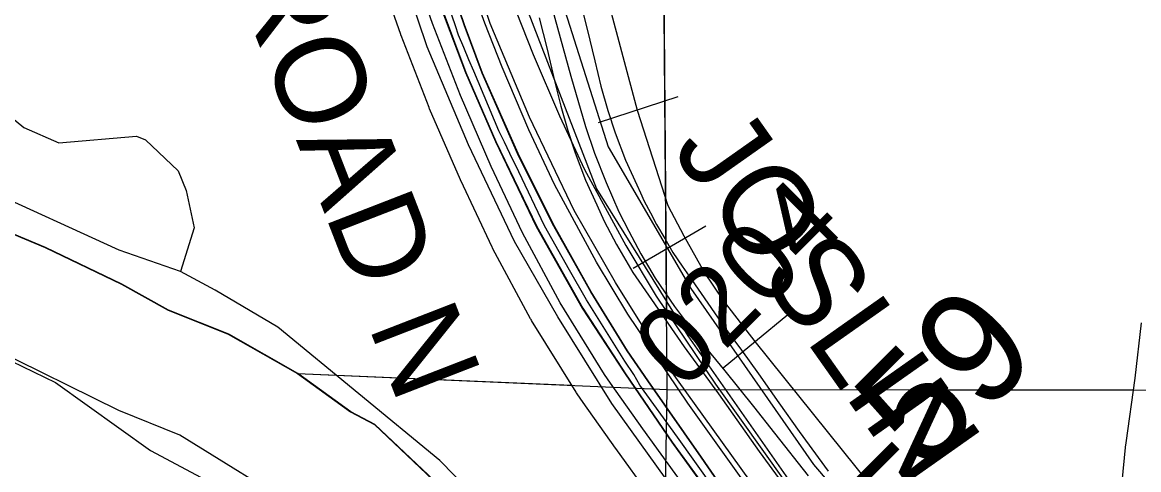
# Model space of a CAD drawing. Extents: x -132.8 to -73.3, y -60 to -26.
# Drawn here: x -124.268 to -123.269, y -45.375 to -44.975 of the extents above; entities that cross this region are included whole.
import ezdxf

# ---------------------------------------------------------------- set-up
doc = ezdxf.new("R2010")
doc.units = 0
for name, color, linetype in [('tdCoClipBndry', 7, 'Continuous'), ('tdCoCoBndry', 7, 'Continuous'), ('tdCoDivCarto', 7, 'Continuous'), ('tdCoHydroRiver', 7, 'Continuous'), ('tdCoInt', 7, 'Continuous'), ('tdCoIntCL', 7, 'Continuous'), ('tdCoIntRte', 7, 'Continuous'), ('tdCoPrimary', 7, 'Continuous'), ('tdCoRRCL', 7, 'Continuous'), ('tdCoSecRdNmbr', 7, 'Continuous'), ('tdCoSecRdTxt', 7, 'Continuous'), ('tdCoSecRteBand', 7, 'Continuous'), ('tdCoSecRteCL', 7, 'Continuous'), ('tdCoSectLine', 7, 'Continuous'), ('tdCoSectLinePart', 7, 'Continuous'), ('tdCoStBndry', 7, 'Continuous'), ('tdCoStBndryPart', 7, 'Continuous'), ('tdCoSurfGravel', 7, 'Continuous'), ('tdCoTwpBndryShd', 7, 'Continuous'), ('tdStHwyIntRefPost1', 7, 'Continuous')]:
    doc.layers.add(name, color=color, linetype=linetype)

msp = doc.modelspace()

# ---------------------------------------------------------------- linework, layer by layer
at = {"layer": 'tdCoClipBndry'}
msp.add_lwpolyline([(-124.01511, -45.41316), (-124.12675, -45.34419), (-124.18134, -45.32205), (-124.40871, -45.21001), (-124.50766, -45.1763), (-124.57794, -45.15917), (-124.65494, -45.14965), (-124.79577, -45.14308), (-124.898, -45.14486), (-125.21642, -45.18326), (-125.4103, -45.23569), (-125.73672, -45.23796), (-125.88496, -45.21905), (-126.11434, -45.13247), (-126.53414, -44.87623), (-126.77109, -44.70765), (-127.14208, -44.40767)], dxfattribs=at)
at = {"layer": 'tdCoCoBndry'}
for p, q in [((-124.24673, -45.17619), (-124.30613, -45.15157)), ((-124.17849, -45.20902), (-124.24673, -45.17619)), ((-124.13678, -45.23238), (-124.17849, -45.20902)), ((-124.08307, -45.25384), (-124.13678, -45.23238)), ((-124.02117, -45.28877), (-124.08307, -45.25384)), ((-123.97374, -45.3233), (-124.02117, -45.28877)), ((-123.95225, -45.33467), (-123.97374, -45.3233)), ((-123.8941, -45.38961), (-123.95225, -45.33467))]:
    msp.add_line(p, q, dxfattribs=at)
for points in [[(-125.23594, -45.08493), (-125.14117, -45.07226), (-125.04956, -45.06338), (-124.95858, -45.05197), (-124.90488, -45.045), (-124.79431, -45.04307), (-124.71752, -45.04881), (-124.64647, -45.04997), (-124.5599, -45.06068), (-124.47965, -45.08023), (-124.41204, -45.10169), (-124.37034, -45.11747), (-124.30651, -45.15157), (-124.24711, -45.17619), (-124.17886, -45.20902), (-124.13716, -45.23238), (-124.08344, -45.25384), (-124.02155, -45.28877), (-123.97412, -45.3233), (-123.95263, -45.33467), (-123.89448, -45.38961)], [(-123.8941, -45.38961), (-123.95225, -45.33467), (-123.97374, -45.3233), (-124.02117, -45.28877), (-124.08307, -45.25384), (-124.13678, -45.23238), (-124.17849, -45.20902), (-124.24673, -45.17619), (-124.30613, -45.15157), (-124.36996, -45.11747), (-124.41166, -45.10169), (-124.47928, -45.08023), (-124.55952, -45.06068), (-124.64609, -45.04997), (-124.71714, -45.04881), (-124.79393, -45.04307), (-124.9045, -45.045), (-124.9582, -45.05197), (-125.04918, -45.06338), (-125.14079, -45.07226), (-125.23556, -45.08493)]]:
    msp.add_lwpolyline(points, dxfattribs=at)
at = {"layer": 'tdCoDivCarto'}
for p, q in [((-123.87221, -44.97694), (-123.88947, -44.92614)), ((-123.89226, -44.96304), (-123.87106, -45.01952)), ((-123.85618, -45.02034), (-123.87221, -44.97694)), ((-123.87106, -45.01952), (-123.84417, -45.08142)), ((-123.82436, -45.0921), (-123.85618, -45.02034)), ((-123.84417, -45.08142), (-123.80768, -45.15737)), ((-123.79305, -45.15499), (-123.82436, -45.0921)), ((-123.75901, -45.2159), (-123.79305, -45.15499)), ((-123.80768, -45.15737), (-123.76649, -45.23037)), ((-123.72646, -45.26867), (-123.75901, -45.2159)), ((-123.76649, -45.23037), (-123.72827, -45.28931)), ((-123.70797, -45.29555), (-123.72646, -45.26867)), ((-123.72827, -45.28931), (-123.68659, -45.35046)), ((-123.66037, -45.36362), (-123.70797, -45.29555)), ((-123.68659, -45.35046), (-123.65626, -45.39214)), ((-123.61855, -45.42416), (-123.66037, -45.36362))]:
    msp.add_line(p, q, dxfattribs=at)
for points in [[(-123.61855, -45.42416), (-123.66037, -45.36362), (-123.70797, -45.29555), (-123.72646, -45.26867), (-123.75901, -45.2159), (-123.79305, -45.15499), (-123.82436, -45.0921), (-123.85618, -45.02034), (-123.87221, -44.97694), (-123.88947, -44.92614), (-123.90722, -44.86843), (-123.93805, -44.76264), (-123.97381, -44.63785), (-124.00266, -44.53674), (-124.03201, -44.43563), (-124.06924, -44.30666), (-124.09982, -44.22059), (-124.14862, -44.09419)], [(-123.61855, -45.42416), (-123.66037, -45.36362), (-123.70797, -45.29555), (-123.72646, -45.26867), (-123.75901, -45.2159), (-123.79305, -45.15499), (-123.82436, -45.0921), (-123.85618, -45.02034), (-123.87221, -44.97694), (-123.88947, -44.92614), (-123.90722, -44.86843), (-123.93805, -44.76264), (-123.97381, -44.63785), (-124.00266, -44.53674), (-124.03201, -44.43563), (-124.06924, -44.30666), (-124.09982, -44.22059), (-124.14862, -44.09419)], [(-123.61855, -45.42416), (-123.66037, -45.36362), (-123.70797, -45.29555), (-123.72646, -45.26867), (-123.75901, -45.2159), (-123.79305, -45.15499), (-123.82436, -45.0921), (-123.85618, -45.02034), (-123.87221, -44.97694), (-123.88947, -44.92614), (-123.90722, -44.86843), (-123.93805, -44.76264), (-123.97381, -44.63785), (-124.00266, -44.53674), (-124.03201, -44.43563), (-124.06924, -44.30666), (-124.09982, -44.22059), (-124.14862, -44.09419)], [(-124.15734, -44.11037), (-124.1443, -44.14431), (-124.10508, -44.24493), (-124.07599, -44.32976), (-124.06834, -44.35836), (-124.0316, -44.48364), (-123.99707, -44.60472), (-123.96255, -44.72507), (-123.93172, -44.83382), (-123.91125, -44.9078), (-123.89226, -44.96304), (-123.87106, -45.01952), (-123.84417, -45.08142), (-123.80768, -45.15737), (-123.76649, -45.23037), (-123.72827, -45.28931), (-123.68659, -45.35046), (-123.65626, -45.39214)], [(-124.15734, -44.11037), (-124.1443, -44.14431), (-124.10508, -44.24493), (-124.07599, -44.32976), (-124.06834, -44.35836), (-124.0316, -44.48364), (-123.99707, -44.60472), (-123.96255, -44.72507), (-123.93172, -44.83382), (-123.91125, -44.9078), (-123.89226, -44.96304), (-123.87106, -45.01952), (-123.84417, -45.08142), (-123.80768, -45.15737), (-123.76649, -45.23037), (-123.72827, -45.28931), (-123.68659, -45.35046), (-123.65626, -45.39214)], [(-124.15734, -44.11037), (-124.1443, -44.14431), (-124.10508, -44.24493), (-124.07599, -44.32976), (-124.06834, -44.35836), (-124.0316, -44.48364), (-123.99707, -44.60472), (-123.96255, -44.72507), (-123.93172, -44.83382), (-123.91125, -44.9078), (-123.89226, -44.96304), (-123.87106, -45.01952), (-123.84417, -45.08142), (-123.80768, -45.15737), (-123.76649, -45.23037), (-123.72827, -45.28931), (-123.68659, -45.35046), (-123.65626, -45.39214)]]:
    msp.add_lwpolyline(points, dxfattribs=at)
at = {"layer": 'tdCoHydroRiver'}
for points in [[(-124.12618, -45.19755), (-124.18089, -45.17863), (-124.30243, -45.1231), (-124.39926, -45.0872), (-124.53842, -45.04063), (-124.66387, -45.01181), (-124.74609, -45.01735), (-124.75858, -45.01226), (-124.77692, -44.99122), (-124.81648, -44.99483), (-124.82945, -45.00708), (-124.84987, -45.00334), (-124.87799, -44.99307), (-124.91759, -44.99825), (-124.94485, -45.01325), (-125.09373, -45.03109), (-125.25981, -45.0437)], [(-124.28004, -45.05747), (-124.26616, -45.06891), (-124.23498, -45.08242), (-124.16536, -45.07652), (-124.15756, -45.0799), (-124.12836, -45.10755), (-124.12097, -45.12512), (-124.11402, -45.15845), (-124.12618, -45.19755)], [(-125.28124, -45.18666), (-125.02725, -45.13553), (-124.95146, -45.13454), (-124.57854, -45.17517), (-124.54411, -45.18562), (-124.4927, -45.20917), (-124.43628, -45.2234), (-124.40627, -45.22269), (-124.38621, -45.23903), (-124.35823, -45.25403), (-124.29709, -45.2684), (-124.23791, -45.29691), (-124.15283, -45.35771), (-124.07199, -45.40104)], [(-123.79148, -45.47215), (-123.89423, -45.36667), (-124.03921, -45.24736), (-124.09509, -45.21421), (-124.12618, -45.19755)]]:
    msp.add_lwpolyline(points, dxfattribs=at)
at = {"layer": 'tdCoInt'}
for points in [[(-123.55308, -45.57692), (-123.74046, -45.31564), (-123.78872, -45.23836), (-123.82739, -45.17068), (-123.86875, -45.08428), (-123.90571, -44.99656), (-123.93096, -44.92117), (-124.01462, -44.62805), (-124.03288, -44.56973), (-124.08447, -44.38971), (-124.10278, -44.32357), (-124.14273, -44.21452), (-124.20021, -44.06525), (-124.29087, -43.83017), (-124.324, -43.74537), (-124.43508, -43.45911), (-124.47376, -43.36588), (-124.49814, -43.31328), (-124.54093, -43.2359), (-124.61351, -43.13317), (-124.65737, -43.06122), (-124.71285, -42.96855), (-124.75858, -42.87103), (-124.76764, -42.84773)], [(-123.50419, -45.54213), (-123.69017, -45.28281), (-123.7373, -45.20743), (-123.77409, -45.14305), (-123.81407, -45.05953), (-123.84932, -44.97587), (-123.87364, -44.90342), (-123.95712, -44.61088), (-123.97527, -44.55295), (-124.02677, -44.37325), (-124.04575, -44.3047), (-124.08652, -44.19353), (-124.14442, -44.04318), (-124.1625, -43.99862), (-124.16218, -43.99944), (-124.23494, -43.80842), (-124.26849, -43.72257), (-124.37939, -43.43676), (-124.41879, -43.3418), (-124.44443, -43.28648)]]:
    msp.add_lwpolyline(points, dxfattribs=at)
at = {"layer": 'tdCoIntCL'}
msp.add_lwpolyline([(-123.64916, -45.39147), (-123.68187, -45.34586), (-123.71532, -45.29922), (-123.71811, -45.29451), (-123.7209, -45.28979), (-123.72901, -45.27773), (-123.76301, -45.22289), (-123.77837, -45.19657), (-123.80074, -45.15687), (-123.82376, -45.10836), (-123.83159, -45.09219), (-123.8365, -45.08205), (-123.84141, -45.0719), (-123.86395, -45.01846), (-123.8683, -45.00815), (-123.87291, -44.99718), (-123.87751, -44.98622), (-123.88014, -44.97788), (-123.89243, -44.94213)], dxfattribs=at)
at = {"layer": 'tdCoIntRte'}
for points in [[(-123.61893, -45.42416), (-123.66075, -45.36362), (-123.70834, -45.29555), (-123.72684, -45.26867), (-123.75939, -45.2159), (-123.79342, -45.15499), (-123.82474, -45.0921), (-123.85656, -45.02034), (-123.87258, -44.97694), (-123.88985, -44.92614), (-123.9076, -44.86843), (-123.93843, -44.76264), (-123.97419, -44.63785), (-124.00304, -44.53674), (-124.03239, -44.43563), (-124.06962, -44.30666), (-124.1002, -44.22059), (-124.149, -44.09419)], [(-123.61893, -45.42416), (-123.66075, -45.36362), (-123.70834, -45.29555), (-123.72684, -45.26867), (-123.75939, -45.2159), (-123.79342, -45.15499), (-123.82474, -45.0921), (-123.85656, -45.02034), (-123.87258, -44.97694), (-123.88985, -44.92614), (-123.9076, -44.86843), (-123.93843, -44.76264), (-123.97419, -44.63785), (-124.00304, -44.53674), (-124.03239, -44.43563), (-124.06962, -44.30666), (-124.1002, -44.22059), (-124.149, -44.09419)], [(-124.14467, -44.14431), (-124.10546, -44.24493), (-124.07636, -44.32976), (-124.06872, -44.35836), (-124.03197, -44.48364), (-123.99745, -44.60472), (-123.96292, -44.72507), (-123.9321, -44.83382), (-123.91163, -44.9078), (-123.89264, -44.96304), (-123.87143, -45.01952), (-123.84455, -45.08142), (-123.80806, -45.15737), (-123.76687, -45.23037), (-123.72865, -45.28931), (-123.68697, -45.35046), (-123.65664, -45.39214)], [(-124.14467, -44.14431), (-124.10546, -44.24493), (-124.07636, -44.32976), (-124.06872, -44.35836), (-124.03197, -44.48364), (-123.99745, -44.60472), (-123.96292, -44.72507), (-123.9321, -44.83382), (-123.91163, -44.9078), (-123.89264, -44.96304), (-123.87143, -45.01952), (-123.84455, -45.08142), (-123.80806, -45.15737), (-123.76687, -45.23037), (-123.72865, -45.28931), (-123.68697, -45.35046), (-123.65664, -45.39214)]]:
    msp.add_lwpolyline(points, dxfattribs=at)
at = {"layer": 'tdCoPrimary'}
for points in [[(-123.61855, -45.42416), (-123.66037, -45.36362), (-123.70797, -45.29555), (-123.72646, -45.26867), (-123.75901, -45.2159), (-123.79305, -45.15499), (-123.82436, -45.0921), (-123.85618, -45.02034), (-123.87221, -44.97694), (-123.88947, -44.92614), (-123.90722, -44.86843), (-123.93805, -44.76264), (-123.97381, -44.63785), (-124.00266, -44.53674), (-124.03201, -44.43563), (-124.06924, -44.30666), (-124.09982, -44.22059), (-124.14862, -44.09419)], [(-123.61855, -45.42416), (-123.66037, -45.36362), (-123.70797, -45.29555), (-123.72646, -45.26867), (-123.75901, -45.2159), (-123.79305, -45.15499), (-123.82436, -45.0921), (-123.85618, -45.02034), (-123.87221, -44.97694), (-123.88947, -44.92614), (-123.90722, -44.86843), (-123.93805, -44.76264), (-123.97381, -44.63785), (-124.00266, -44.53674), (-124.03201, -44.43563), (-124.06924, -44.30666), (-124.09982, -44.22059), (-124.14862, -44.09419)], [(-123.61855, -45.42416), (-123.66037, -45.36362), (-123.70797, -45.29555), (-123.72646, -45.26867), (-123.75901, -45.2159), (-123.79305, -45.15499), (-123.82436, -45.0921), (-123.85618, -45.02034), (-123.87221, -44.97694), (-123.88947, -44.92614), (-123.90722, -44.86843), (-123.93805, -44.76264), (-123.97381, -44.63785), (-124.00266, -44.53674), (-124.03201, -44.43563), (-124.06924, -44.30666), (-124.09982, -44.22059), (-124.14862, -44.09419)], [(-124.15734, -44.11037), (-124.1443, -44.14431), (-124.10508, -44.24493), (-124.07599, -44.32976), (-124.06834, -44.35836), (-124.0316, -44.48364), (-123.99707, -44.60472), (-123.96255, -44.72507), (-123.93172, -44.83382), (-123.91125, -44.9078), (-123.89226, -44.96304), (-123.87106, -45.01952), (-123.84417, -45.08142), (-123.80768, -45.15737), (-123.76649, -45.23037), (-123.72827, -45.28931), (-123.68659, -45.35046), (-123.65626, -45.39214)], [(-124.15734, -44.11037), (-124.1443, -44.14431), (-124.10508, -44.24493), (-124.07599, -44.32976), (-124.06834, -44.35836), (-124.0316, -44.48364), (-123.99707, -44.60472), (-123.96255, -44.72507), (-123.93172, -44.83382), (-123.91125, -44.9078), (-123.89226, -44.96304), (-123.87106, -45.01952), (-123.84417, -45.08142), (-123.80768, -45.15737), (-123.76649, -45.23037), (-123.72827, -45.28931), (-123.68659, -45.35046), (-123.65626, -45.39214)], [(-124.1443, -44.14431), (-124.10508, -44.24493), (-124.07599, -44.32976), (-124.06834, -44.35836), (-124.0316, -44.48364), (-123.99707, -44.60472), (-123.96255, -44.72507), (-123.93172, -44.83382), (-123.91125, -44.9078), (-123.89226, -44.96304), (-123.87106, -45.01952), (-123.84417, -45.08142), (-123.80768, -45.15737), (-123.76649, -45.23037), (-123.72827, -45.28931), (-123.68659, -45.35046), (-123.65626, -45.39214)]]:
    msp.add_lwpolyline(points, dxfattribs=at)
at = {"layer": 'tdCoRRCL'}
for p, q in [((-123.68134, -45.04128), (-123.75257, -45.06476)), ((-123.72135, -45.19464), (-123.65657, -45.15685)), ((-123.58323, -45.2363), (-123.64109, -45.28402))]:
    msp.add_line(p, q, dxfattribs=at)
for points in [[(-124.56441, -39.58277), (-124.59502, -40.99697), (-124.62126, -41.69986), (-124.64443, -42.5874), (-124.61743, -42.70169), (-124.59894, -42.77948), (-124.57448, -42.87004), (-124.36447, -43.41034), (-124.28789, -43.62059), (-124.20724, -43.85618), (-124.00071, -44.40901), (-123.83109, -44.9246), (-123.75422, -45.12382), (-123.67243, -45.25532), (-123.34073, -45.72941), (-123.31155, -45.76015), (-123.21558, -45.95355), (-123.18597, -46.02848), (-123.11918, -46.43252), (-123.02482, -47.17174), (-122.96612, -47.70495)], [(-123.58232, -40.4714), (-123.59666, -41.26294), (-123.63242, -42.39151), (-123.63672, -42.43557), (-123.64126, -42.54903), (-123.65963, -42.64794), (-123.68385, -42.72933), (-123.79029, -42.93793), (-123.83057, -43.02995), (-123.8684, -43.14885), (-123.90323, -43.27414), (-123.92804, -43.49908), (-123.92555, -43.88723), (-123.90748, -43.92083), (-123.9211, -44.44265), (-123.92029, -44.53259), (-123.90156, -44.60092), (-123.84732, -44.7601), (-123.74377, -45.08623), (-123.66974, -45.2128), (-123.56021, -45.37027), (-123.43616, -45.51551)], [(-123.45627, -45.45467), (-123.61223, -45.2604), (-123.6285, -45.23945), (-123.64056, -45.22346), (-123.65786, -45.19803), (-123.67594, -45.16618), (-123.6901, -45.13879), (-123.71762, -45.05358), (-123.78172, -44.81317), (-123.85988, -44.57574), (-123.87319, -44.53731), (-123.88574, -44.49111), (-123.89252, -44.46047), (-123.89503, -44.44007), (-123.89608, -44.3976), (-123.89594, -44.34225), (-123.89553, -44.09233)], [(-123.79622, -44.95329), (-123.77708, -45.02276), (-123.76398, -45.06785), (-123.75611, -45.0917), (-123.74563, -45.11818), (-123.73409, -45.1444), (-123.72518, -45.1617), (-123.71469, -45.18188), (-123.70185, -45.20364), (-123.68455, -45.22907), (-123.66043, -45.26105), (-123.63946, -45.28648), (-123.61377, -45.31846), (-123.59516, -45.34231), (-123.56501, -45.38032)], [(-123.8055, -44.97058), (-123.79842, -44.99863), (-123.7916, -45.02694), (-123.7861, -45.04975), (-123.77981, -45.07151), (-123.77325, -45.09143), (-123.76408, -45.11581), (-123.75386, -45.13809), (-123.7473, -45.15251), (-123.73635, -45.17336), (-123.73629, -45.17348), (-123.72161, -45.19864), (-123.7051, -45.22276), (-123.67574, -45.26497), (-123.64507, -45.30717), (-123.60889, -45.35881), (-123.58294, -45.3942)], [(-123.76616, -44.96672), (-123.76262, -44.98075), (-123.7558, -45.00906), (-123.7503, -45.03186), (-123.744, -45.05362), (-123.73745, -45.07354), (-123.72828, -45.09792), (-123.72316, -45.10906), (-123.71805, -45.12021), (-123.71478, -45.12741), (-123.7115, -45.13462), (-123.70602, -45.14505), (-123.70055, -45.15548), (-123.69315, -45.16818), (-123.68581, -45.18076), (-123.67755, -45.19282), (-123.66929, -45.20488), (-123.65461, -45.22598), (-123.63993, -45.24708), (-123.6246, -45.26818), (-123.60926, -45.28929), (-123.59118, -45.31511), (-123.57309, -45.34093), (-123.54714, -45.37632)]]:
    msp.add_lwpolyline(points, dxfattribs=at)
at = {"layer": 'tdCoSecRteBand'}
for points in [[(-123.64653, -45.48115), (-123.73701, -45.35592), (-123.7371, -45.35578), (-123.7372, -45.35565), (-123.76608, -45.31471), (-123.77148, -45.30707), (-123.772, -45.30633), (-123.77247, -45.30556), (-123.81218, -45.24145), (-123.81265, -45.24068), (-123.81307, -45.23989), (-123.84686, -45.17726), (-123.84726, -45.17651), (-123.84762, -45.17575), (-123.87548, -45.11632), (-123.87566, -45.11595), (-123.87582, -45.11557), (-123.90344, -45.05219), (-123.90369, -45.05162), (-123.90392, -45.05103), (-123.92883, -44.98667), (-123.92902, -44.98618), (-123.92919, -44.98568), (-123.94546, -44.93883)], [(-123.82598, -44.96504), (-123.81078, -45.00339), (-123.78722, -45.05854), (-123.76487, -45.10636), (-123.72811, -45.17432), (-123.70099, -45.21967), (-123.64791, -45.29831), (-123.56331, -45.41686)], [(-123.28894, -45.43472), (-123.2808, -45.3521), (-123.28074, -45.3515), (-123.28065, -45.35089), (-123.27257, -45.29309), (-123.267, -45.24368)]]:
    msp.add_lwpolyline(points, dxfattribs=at)
at = {"layer": 'tdCoSecRteCL'}
for points in [[(-123.58773, -45.43429), (-123.67256, -45.31542), (-123.72632, -45.23577), (-123.75419, -45.18916), (-123.79167, -45.11986), (-123.81461, -45.07079), (-123.83853, -45.01481), (-123.85406, -44.9756), (-123.86319, -44.94995), (-123.88588, -44.88189), (-123.90067, -44.82837), (-123.93618, -44.70581), (-123.9421, -44.68485), (-123.94531, -44.66808), (-123.94679, -44.65008), (-123.94703, -44.61728), (-123.94605, -44.58103), (-123.94358, -44.51494), (-123.94334, -44.45772), (-123.94728, -44.33763), (-123.95006, -44.29303), (-123.95098, -44.27819), (-123.95147, -44.22616), (-123.94876, -44.14601)], [(-123.62218, -45.46363), (-123.71269, -45.33835), (-123.74157, -45.29741), (-123.74697, -45.28977), (-123.78667, -45.22565), (-123.82045, -45.16301), (-123.84832, -45.10358), (-123.87594, -45.0402), (-123.90085, -44.97584), (-123.91712, -44.92899), (-123.94277, -44.84095), (-123.97878, -44.71468), (-124.01478, -44.58916), (-124.02711, -44.54847), (-124.03278, -44.53762), (-124.04166, -44.52726), (-124.05128, -44.51962), (-124.06238, -44.51395), (-124.07224, -44.51049), (-124.08358, -44.50877), (-124.24769, -44.50526)]]:
    msp.add_lwpolyline(points, dxfattribs=at)
at = {"layer": 'tdCoSectLine'}
for points in [[(-123.69087, -45.30309), (-123.69916, -44.29255)], [(-124.71752, -45.04881), (-124.64647, -45.04997), (-124.5599, -45.06068), (-124.47965, -45.08023), (-124.41204, -45.10169), (-124.37034, -45.11747), (-124.30651, -45.15157), (-124.24711, -45.17619), (-124.17886, -45.20902), (-124.13716, -45.23238), (-124.08344, -45.25384), (-124.02155, -45.28877)], [(-124.02155, -45.28877), (-123.69087, -45.30309)], [(-124.02155, -45.28877), (-123.97412, -45.3233), (-123.95263, -45.33467), (-123.89448, -45.38961), (-123.85657, -45.43137), (-123.79202, -45.50244), (-123.77088, -45.52572), (-123.72719, -45.57383), (-123.69602, -45.60815)], [(-123.69602, -45.60815), (-123.69087, -45.30309)], [(-123.69087, -45.30309), (-122.72574, -45.3043)]]:
    msp.add_lwpolyline(points, dxfattribs=at)
at = {"layer": 'tdCoSectLinePart'}
for points in [[(-123.69144, -45.23441), (-123.69916, -44.29255)], [(-124.71752, -45.04881), (-124.64647, -45.04997), (-124.5599, -45.06068), (-124.47965, -45.08023), (-124.41204, -45.10169), (-124.37034, -45.11747), (-124.30651, -45.15157), (-124.24711, -45.17619), (-124.17886, -45.20902), (-124.13716, -45.23238), (-124.08344, -45.25384), (-124.02155, -45.28877)], [(-124.02155, -45.28877), (-123.77662, -45.29937)], [(-124.02155, -45.28877), (-123.97412, -45.3233), (-123.95263, -45.33467), (-123.89448, -45.38961), (-123.85657, -45.43137), (-123.79202, -45.50244), (-123.77088, -45.52572), (-123.72719, -45.57383), (-123.69602, -45.60815)], [(-123.64488, -45.30315), (-123.27499, -45.30361)]]:
    msp.add_lwpolyline(points, dxfattribs=at)
at = {"layer": 'tdCoStBndry'}
msp.add_lwpolyline([(-125.23594, -45.08493), (-125.14117, -45.07226), (-125.04956, -45.06338), (-124.95858, -45.05197), (-124.90488, -45.045), (-124.79431, -45.04307), (-124.71752, -45.04881), (-124.64647, -45.04997), (-124.5599, -45.06068), (-124.47965, -45.08023), (-124.41204, -45.10169), (-124.37034, -45.11747), (-124.30651, -45.15157), (-124.24711, -45.17619), (-124.17886, -45.20902), (-124.13716, -45.23238), (-124.08344, -45.25384), (-124.02155, -45.28877), (-123.97412, -45.3233), (-123.95263, -45.33467), (-123.89448, -45.38961)], dxfattribs=at)
at = {"layer": 'tdCoStBndryPart'}
msp.add_lwpolyline([(-125.23594, -45.08493), (-125.14117, -45.07226), (-125.04956, -45.06338), (-124.95858, -45.05197), (-124.90488, -45.045), (-124.79431, -45.04307), (-124.71752, -45.04881), (-124.64647, -45.04997), (-124.5599, -45.06068), (-124.47965, -45.08023), (-124.41204, -45.10169), (-124.37034, -45.11747), (-124.30651, -45.15157), (-124.24711, -45.17619), (-124.17886, -45.20902), (-124.13716, -45.23238), (-124.08344, -45.25384), (-124.02155, -45.28877), (-123.97412, -45.3233), (-123.95263, -45.33467), (-123.89448, -45.38961)], dxfattribs=at)
at = {"layer": 'tdCoSurfGravel'}
for points in [[(-123.58773, -45.43429), (-123.67256, -45.31542), (-123.72632, -45.23577), (-123.75419, -45.18916), (-123.79167, -45.11986), (-123.81461, -45.07079), (-123.83853, -45.01481), (-123.85406, -44.9756), (-123.86319, -44.94995), (-123.88588, -44.88189), (-123.90067, -44.82837), (-123.93618, -44.70581), (-123.9421, -44.68485), (-123.94531, -44.66808), (-123.94679, -44.65008), (-123.94703, -44.61728), (-123.94605, -44.58103), (-123.94358, -44.51494), (-123.94334, -44.45772), (-123.94728, -44.33763), (-123.95006, -44.29303)], [(-123.74157, -45.29741), (-123.74697, -45.28977), (-123.78667, -45.22565), (-123.82045, -45.16301), (-123.84832, -45.10358), (-123.87594, -45.0402), (-123.90085, -44.97584), (-123.91712, -44.92899), (-123.94277, -44.84095), (-123.97878, -44.71468), (-124.01478, -44.58916), (-124.02711, -44.54847), (-124.03278, -44.53762), (-124.04166, -44.52726), (-124.05128, -44.51962), (-124.06238, -44.51395), (-124.07224, -44.51049), (-124.08358, -44.50877), (-124.24769, -44.50526)], [(-123.24667, -46.25927), (-123.25942, -46.16966), (-123.26756, -46.1233), (-123.27718, -46.08064), (-123.28482, -46.05055), (-123.29518, -46.01529), (-123.30973, -45.97041), (-123.32724, -45.92602), (-123.34574, -45.88335), (-123.36448, -45.84562), (-123.38544, -45.8074), (-123.41454, -45.75906), (-123.43871, -45.72257), (-123.46386, -45.68557), (-123.54845, -45.56646), (-123.62218, -45.46363), (-123.71269, -45.33835), (-123.74157, -45.29741)]]:
    msp.add_lwpolyline(points, dxfattribs=at)
at = {"layer": 'tdCoTwpBndryShd'}
msp.add_lwpolyline([(-123.89448, -45.38961), (-123.95263, -45.33467), (-123.97412, -45.3233), (-124.02155, -45.28877), (-124.08344, -45.25384), (-124.13716, -45.23238), (-124.17886, -45.20902), (-124.24711, -45.17619), (-124.30651, -45.15157), (-124.37034, -45.11747), (-124.41204, -45.10169), (-124.47965, -45.08023), (-124.5599, -45.06068), (-124.64647, -45.04997), (-124.71752, -45.04881), (-124.79431, -45.04307), (-124.90488, -45.045), (-124.95858, -45.05197), (-125.04956, -45.06338), (-125.14117, -45.07226), (-125.23594, -45.08493)], dxfattribs=at)

# ---------------------------------------------------------------- texts
at = {"layer": 'tdCoSecRdNmbr'}
msp.add_text('0204', height=0.07, rotation=44.90754, dxfattribs=at).set_placement((-123.67721, -45.30604))
at = {"layer": 'tdCoSecRdTxt'}
for s, rotation, p in [('RIVERROAD N', 291.21713, (-124.19941, -44.62551)), ('JOSLIN AVE', 305.20215, (-123.6881, -45.08832))]:
    msp.add_text(s, height=0.08, rotation=rotation, dxfattribs=at).set_placement(p)
at = {"layer": 'tdStHwyIntRefPost1'}
msp.add_text('‒‒59', height=0.1, rotation=45, dxfattribs=at).set_placement((-123.56574, -45.48445))

doc.saveas('drawing.dxf')
